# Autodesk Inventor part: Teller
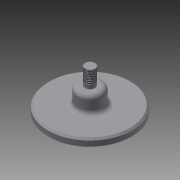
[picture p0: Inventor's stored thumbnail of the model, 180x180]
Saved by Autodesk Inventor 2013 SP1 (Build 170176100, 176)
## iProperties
Created: 2012-11
Part Number: Teller
Material: Allgemein
Document SubType Name: Modeling
Designer: macuser
Density: 1 g/cm^3
Author: macuser
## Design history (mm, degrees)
sketch "Skizze1"
  geometry: L1 (-70, 0)-(70, 0) reference; L2 (0, -70)-(0, 70) reference; C1 r 50 at (0, 0); 1 further point
  constraints: 1 centre point, 1 coincident
  dimensions: "d0" = 100 diameter of C1
extrude "Extrusion1" new body sketch "Skizze1" distance "d1" = 10; taper "d2" = 0 deg
sketch "Skizze2"
  geometry: C1 r 50 at (0, 0) reference; C2 r 15 at (0, 0)
  constraints: 1 centre point, 1 coincident
  dimensions: "d3" = 30 diameter of C2
extrude "Extrusion2" join sketch "Skizze2" distance "d4" = 20; taper "d5" = 0 deg
sketch "Skizze3"
  geometry: C1 r 15 at (0, 0) reference; C2 r 6 at (0, 0)
  constraints: 1 centre point, 1 coincident
  dimensions: "d7" = 12 diameter of C2
extrude "Extrusion3" join sketch "Skizze3" distance "d8" = 20; taper "d9" = 0 deg
feature "Gewinde1" dims "d10" = 20, "d11" = 5
fillet "Rundung1" dims "d12" = 5
fillet "Rundung2" dims "d13" = 5
chamfer "Fase1" distance "d14" = 2; stored, may be unused: second distance "d15" = 2, angle "d16" = 45 deg
node "Volumenkörper1"
